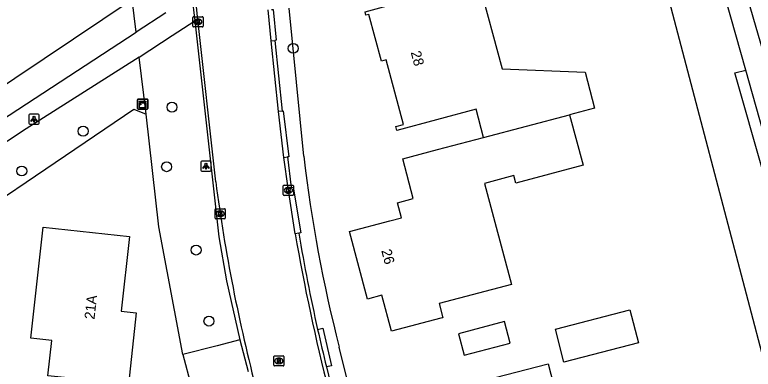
# Model space of a CAD drawing. Extents: x 162157 to 163165, y 378998 to 380775.
# Drawn here: x 162660.8 to 162733.3, y 380410.9 to 380445.7 of the extents above; entities that cross this region are included whole.
import ezdxf

# ---------------------------------------------------------------- set-up
doc = ezdxf.new("R2010")
doc.units = 0
for name, color, linetype in [('IMGEO_Boom', 7, 'Continuous'), ('IMGEO_Gemengd_bos', 7, 'Continuous'), ('IMGEO_Groenvoorziening', 7, 'Continuous'), ('IMGEO_Hek', 7, 'Continuous'), ('IMGEO_Kast', 7, 'Continuous'), ('IMGEO_Kolk', 7, 'Continuous'), ('IMGEO_Lichtpunt', 7, 'Continuous'), ('IMGEO_Pand', 7, 'Continuous'), ('IMGEO_Pand_nummerreeks', 7, 'Continuous'), ('IMGEO_Rijbaan_lokaal_gesloten', 7, 'Continuous'), ('IMGEO_Rijbaan_lokaal_open', 7, 'Continuous'), ('IMGEO_Rioolput', 7, 'Continuous'), ('IMGEO_Voetpad_halfverhard', 7, 'Continuous'), ('IMGEO_Voetpad_open', 7, 'Continuous')]:
    doc.layers.add(name, color=color, linetype=linetype)

msp = doc.modelspace()

# ---------------------------------------------------------------- linework, layer by layer
at = {"layer": 'IMGEO_Boom'}
for centre in [(162688.13, 380442.41), (162676.236, 380436.636), (162667.518, 380434.283), (162675.71, 380430.795), (162661.503, 380430.375), (162678.6, 380422.62), (162679.864, 380415.65)]:
    msp.add_circle(centre, 0.489, dxfattribs=at)
at = {"layer": 'IMGEO_Gemengd_bos'}
for points in [[(162732.512, 380440.284), (162726.017, 380463.29), (162725.222, 380467.154)], [(162794.037, 380217.15), (162795.456, 380217.538), (162786.56, 380250), (162786.126, 380251.585), (162745.395, 380400.219), (162739.025, 380425.583), (162728.963, 380460.227), (162727.791, 380464.262)], [(162739.846, 380409.655), (162737.08, 380420.274), (162731.457, 380440.006), (162732.512, 380440.284)], [(162794.037, 380217.15), (162784.914, 380250), (162784.538, 380251.354), (162744.134, 380396.843), (162740.791, 380409.902), (162740.789, 380409.911), (162737.886, 380421.251), (162732.513, 380440.281), (162732.512, 380440.284)]]:
    msp.add_lwpolyline(points, dxfattribs=at)
at = {"layer": 'IMGEO_Groenvoorziening'}
for points in [[(162613.427, 380456.794), (162617.964, 380424.039), (162634.993, 380422.187), (162672.345, 380447.227)], [(162672.73, 380443.999), (162672.345, 380447.227)], [(162673.692, 380435.944), (162673.022, 380441.552)], [(162645.264, 380394.472), (162647.636, 380419.636), (162649.415, 380420.824), (162672.481, 380436.433), (162673.692, 380435.944)], [(162677.305, 380412.375), (162674.933, 380424.891), (162673.692, 380435.944)]]:
    msp.add_lwpolyline(points, dxfattribs=at)
at = {"layer": 'IMGEO_Hek'}
msp.add_lwpolyline([(162778.738, 380250.508), (162768.177, 380283.038), (162722.067, 380458.358), (162720.737, 380463.414)], dxfattribs=at)
at = {"layer": 'IMGEO_Kast'}
for p, q in [((162672.937, 380437.438), (162673.778, 380437.438)), ((162673.778, 380437.438), (162672.937, 380437.438)), ((162672.862, 380436.513), (162672.862, 380437.354)), ((162672.862, 380437.354), (162672.862, 380436.513)), ((162673.862, 380437.363), (162673.862, 380436.522)), ((162673.862, 380436.522), (162673.862, 380437.363)), ((162673.787, 380436.438), (162672.946, 380436.438)), ((162672.946, 380436.438), (162673.787, 380436.438))]:
    msp.add_line(p, q, dxfattribs=at)
for points in [[(162673.057, 380437.228), (162673.657, 380437.228), (162673.657, 380437.143), (162673.057, 380437.143), (162673.057, 380437.228)], [(162673.057, 380437.053), (162673.657, 380437.053), (162673.657, 380436.564), (162673.057, 380436.564), (162673.057, 380437.053)]]:
    msp.add_lwpolyline(points, dxfattribs=at)
msp.add_circle((162673.141, 380436.902), 0.0377, dxfattribs=at)
for centre, start, end in [((162672.94, 380437.36), 92.4484, 184.28452), ((162672.94, 380437.36), 92.4484, 184.28452), ((162673.784, 380437.36), 2.4484, 94.28452), ((162673.784, 380437.36), 2.4484, 94.28452), ((162672.94, 380436.516), 182.4484, 274.28452), ((162672.94, 380436.516), 182.4484, 274.28452), ((162673.784, 380436.516), 272.4484, 4.28452), ((162673.784, 380436.516), 272.4484, 4.28452)]:
    msp.add_arc(centre, 0.0779, start, end, dxfattribs=at)
at = {"layer": 'IMGEO_Kolk'}
for p, q in [((162678.278, 380444.583), (162678.278, 380445.435)), ((162678.353, 380445.509), (162679.205, 380445.509)), ((162679.279, 380445.435), (162679.279, 380444.583)), ((162678.789, 380444.729), (162678.764, 380444.729)), ((162678.766, 380445.289), (162678.791, 380445.289)), ((162679.205, 380444.509), (162678.353, 380444.509)), ((162687.155, 380428.058), (162687.155, 380428.91)), ((162687.23, 380428.984), (162688.082, 380428.984)), ((162687.643, 380428.764), (162687.668, 380428.764)), ((162688.156, 380428.91), (162688.156, 380428.058)), ((162687.666, 380428.204), (162687.641, 380428.204)), ((162688.082, 380427.984), (162687.23, 380427.984)), ((162680.465, 380425.753), (162680.465, 380426.605)), ((162680.54, 380426.679), (162681.392, 380426.679)), ((162681.466, 380426.605), (162681.466, 380425.753)), ((162680.976, 380425.899), (162680.951, 380425.899)), ((162680.953, 380426.459), (162680.978, 380426.459)), ((162681.392, 380425.679), (162680.54, 380425.679))]:
    msp.add_line(p, q, dxfattribs=at)
for points in [[(162678.278, 380444.583), (162678.278, 380445.435)], [(162678.353, 380445.509), (162679.205, 380445.509)], [(162679.279, 380445.435), (162679.279, 380444.583)], [(162678.599, 380445.209), (162678.722, 380445.209), (162678.722, 380445.058), (162678.852, 380445.209), (162679.016, 380445.209), (162678.87, 380445.058), (162679.023, 380444.809), (162678.871, 380444.809), (162678.786, 380444.973), (162678.722, 380444.906), (162678.722, 380444.809), (162678.599, 380444.809), (162678.599, 380445.209)], [(162679.205, 380444.509), (162678.353, 380444.509)], [(162687.155, 380428.058), (162687.155, 380428.91)], [(162687.23, 380428.984), (162688.082, 380428.984)], [(162688.156, 380428.91), (162688.156, 380428.058)], [(162687.476, 380428.684), (162687.599, 380428.684), (162687.599, 380428.533), (162687.729, 380428.684), (162687.893, 380428.684), (162687.747, 380428.533), (162687.9, 380428.284), (162687.748, 380428.284), (162687.663, 380428.448), (162687.599, 380428.381), (162687.599, 380428.284), (162687.476, 380428.284), (162687.476, 380428.684)], [(162688.082, 380427.984), (162687.23, 380427.984)], [(162680.465, 380425.753), (162680.465, 380426.605)], [(162680.54, 380426.679), (162681.392, 380426.679)], [(162681.466, 380426.605), (162681.466, 380425.753)], [(162680.786, 380426.379), (162680.909, 380426.379), (162680.909, 380426.228), (162681.039, 380426.379), (162681.203, 380426.379), (162681.057, 380426.228), (162681.21, 380425.979), (162681.058, 380425.979), (162680.973, 380426.143), (162680.909, 380426.076), (162680.909, 380425.979), (162680.786, 380425.979), (162680.786, 380426.379)], [(162681.392, 380425.679), (162680.54, 380425.679)]]:
    msp.add_lwpolyline(points, dxfattribs=at)
for centre, start, end in [((162678.355, 380445.433), 91.55205, 178.44795), ((162678.355, 380445.433), 91.55205, 178.44795), ((162679.203, 380445.433), 1.55205, 88.44795), ((162679.203, 380445.433), 1.55205, 88.44795), ((162678.355, 380444.585), 181.55205, 268.44795), ((162678.355, 380444.585), 181.55205, 268.44795), ((162679.203, 380444.585), 271.55205, 358.44795), ((162679.203, 380444.585), 271.55205, 358.44795), ((162687.232, 380428.908), 91.55205, 178.44795), ((162687.232, 380428.908), 91.55205, 178.44795), ((162688.08, 380428.908), 1.55205, 88.44795), ((162688.08, 380428.908), 1.55205, 88.44795), ((162687.232, 380428.06), 181.55205, 268.44795), ((162687.232, 380428.06), 181.55205, 268.44795), ((162688.08, 380428.06), 271.55205, 358.44795), ((162688.08, 380428.06), 271.55205, 358.44795), ((162680.542, 380426.603), 91.55205, 178.44795), ((162680.542, 380426.603), 91.55205, 178.44795), ((162681.39, 380426.603), 1.55205, 88.44795), ((162681.39, 380426.603), 1.55205, 88.44795), ((162680.542, 380425.755), 181.55205, 268.44795), ((162680.542, 380425.755), 181.55205, 268.44795), ((162681.39, 380425.755), 271.55205, 358.44795), ((162681.39, 380425.755), 271.55205, 358.44795)]:
    msp.add_arc(centre, 0.0765, start, end, dxfattribs=at)
for centre, major_axis, ratio, start_param, end_param in [((162678.765, 380445.009), (-0.387, 0.002), 0.722429, 4.712389, 7.853982), ((162678.79, 380445.009), (-0.39, 0.002), 0.717154, 1.570796, 4.712389), ((162687.642, 380428.484), (-0.387, 0.002), 0.722429, 4.712389, 7.853982), ((162687.667, 380428.484), (-0.39, 0.002), 0.717154, 1.570796, 4.712389), ((162680.952, 380426.179), (-0.387, 0.002), 0.722429, 4.712389, 7.853982), ((162680.977, 380426.179), (-0.39, 0.002), 0.717154, 1.570796, 4.712389)]:
    msp.add_ellipse(centre, major_axis=major_axis, ratio=ratio, start_param=start_param, end_param=end_param, dxfattribs=at)
at = {"layer": 'IMGEO_Lichtpunt'}
for p, q in [((162663.107, 380435.956), (162662.299, 380435.956)), ((162663.107, 380435.956), (162662.299, 380435.956)), ((162662.205, 380435.861), (162662.205, 380435.054)), ((162662.205, 380435.861), (162662.205, 380435.054)), ((162663.201, 380435.054), (162663.201, 380435.861)), ((162663.201, 380435.054), (162663.201, 380435.861)), ((162662.299, 380434.96), (162663.107, 380434.96)), ((162662.299, 380434.96), (162663.107, 380434.96)), ((162679.069, 380431.251), (162679.069, 380430.444)), ((162679.069, 380431.251), (162679.069, 380430.444)), ((162679.971, 380431.346), (162679.163, 380431.346)), ((162679.971, 380431.346), (162679.163, 380431.346)), ((162680.065, 380430.444), (162680.065, 380431.251)), ((162680.065, 380430.444), (162680.065, 380431.251)), ((162679.163, 380430.35), (162679.971, 380430.35)), ((162679.163, 380430.35), (162679.971, 380430.35))]:
    msp.add_line(p, q, dxfattribs=at)
for points in [[(162662.579, 380435.525), (162662.618, 380435.497), (162662.43, 380435.235), (162662.392, 380435.262), (162662.579, 380435.525)], [(162662.681, 380435.477), (162662.728, 380435.477), (162662.728, 380435.155), (162662.681, 380435.155), (162662.681, 380435.477)], [(162662.791, 380435.497), (162662.829, 380435.524), (162663.016, 380435.262), (162662.977, 380435.234), (162662.791, 380435.497)], [(162679.443, 380430.915), (162679.482, 380430.887), (162679.294, 380430.625), (162679.256, 380430.652), (162679.443, 380430.915)], [(162679.655, 380430.887), (162679.693, 380430.914), (162679.88, 380430.652), (162679.841, 380430.624), (162679.655, 380430.887)], [(162679.545, 380430.867), (162679.592, 380430.867), (162679.592, 380430.545), (162679.545, 380430.545), (162679.545, 380430.867)]]:
    msp.add_lwpolyline(points, dxfattribs=at)
for centre in [(162662.704, 380435.659), (162679.568, 380431.049)]:
    msp.add_circle(centre, 0.0994, dxfattribs=at)
for centre, start, end in [((162662.299, 380435.861), 90, 180), ((162662.299, 380435.861), 90, 180), ((162663.107, 380435.861), 0, 90), ((162663.107, 380435.861), 0, 90), ((162662.299, 380435.054), 180, 270), ((162662.299, 380435.054), 180, 270), ((162663.107, 380435.054), 270, 0), ((162663.107, 380435.054), 270, 360), ((162679.163, 380431.251), 90, 180), ((162679.163, 380431.251), 90, 180), ((162679.971, 380431.251), 0, 90), ((162679.971, 380431.251), 0, 90), ((162679.163, 380430.444), 180, 270), ((162679.163, 380430.444), 180, 270), ((162679.971, 380430.444), 270, 0), ((162679.971, 380430.444), 270, 360)]:
    msp.add_arc(centre, 0.0946, start, end, dxfattribs=at)
at = {"layer": 'IMGEO_Pand'}
for points in [[(162696.861, 380452.692), (162702.175, 380454.118), (162703.738, 380448.295), (162706.318, 380448.988), (162708.621, 380440.412), (162716.751, 380440.068), (162717.69, 380436.537), (162715.243, 380435.893)], [(162706.789, 380433.67), (162706.058, 380436.437), (162698.3, 380434.356), (162698.195, 380434.749), (162698.934, 380434.947), (162697.232, 380441.287), (162696.774, 380441.164), (162695.547, 380445.737), (162695.259, 380445.659), (162695.169, 380445.994), (162698.424, 380446.868), (162696.861, 380452.692)], [(162715.243, 380435.893), (162716.554, 380430.941), (162709.956, 380429.188), (162709.761, 380429.922), (162706.898, 380429.165), (162709.524, 380419.236), (162702.437, 380417.361), (162702.801, 380415.984), (162702.601, 380415.931), (162697.767, 380414.652), (162696.833, 380418.182), (162695.411, 380417.806), (162693.655, 380424.439), (162697.616, 380425.487), (162698.745, 380425.786), (162698.354, 380427.266), (162699.909, 380427.691), (162698.881, 380431.579), (162702.293, 380432.481), (162706.789, 380433.67)], [(162706.789, 380433.67), (162715.243, 380435.893)], [(162664.053, 380410.294), (162664.435, 380413.763), (162662.403, 380413.987), (162663.051, 380419.867), (162663.601, 380424.868), (162672.065, 380423.935), (162671.259, 380416.618), (162672.73, 380416.456), (162671.955, 380409.424), (162666.986, 380409.971), (162664.053, 380410.294)], [(162713.848, 380414.862), (162721.142, 380416.758), (162721.981, 380413.529), (162714.687, 380411.633), (162713.848, 380414.862)], [(162704.325, 380414.413), (162704.884, 380412.297), (162709.413, 380413.494), (162708.853, 380415.609), (162704.325, 380414.413)], [(162702.207, 380399.787), (162701.196, 380399.524), (162699.041, 380407.797), (162703.88, 380409.057), (162713.128, 380411.466), (162714.149, 380407.547), (162708.903, 380406.18), (162710.038, 380401.823)]]:
    msp.add_lwpolyline(points, dxfattribs=at)
at = {"layer": 'IMGEO_Rijbaan_lokaal_gesloten'}
for points in [[(162678.198, 380447.57), (162678.473, 380445.123)], [(162680.525, 380429.323), (162678.724, 380445.517), (162678.557, 380447.491), (162678.535, 380447.716)], [(162685.972, 380443.152), (162685.661, 380446.176)], [(162678.473, 380445.123), (162680.83, 380423.933), (162681.587, 380419.614), (162682.894, 380413.81)], [(162686.685, 380436.218), (162685.972, 380443.152)], [(162687.211, 380431.709), (162686.685, 380436.218)], [(162687.622, 380428.707), (162687.211, 380431.709)], [(162688.33, 380424.21), (162687.622, 380428.707)], [(162682.894, 380413.81), (162683.705, 380410.707)]]:
    msp.add_lwpolyline(points, dxfattribs=at)
for centre, radius, start, end in [((162845.64, 380450.967), 166.527, 187.46797, 194.71182), ((162875.43, 380455.958), 189.775, 189.6306, 194.40292)]:
    msp.add_arc(centre, radius, start, end, dxfattribs=at)
at = {"layer": 'IMGEO_Rijbaan_lokaal_open'}
for points in [[(162685.972, 380443.152), (162686.321, 380443.188)], [(162686.321, 380443.188), (162687.032, 380436.26)], [(162687.032, 380436.26), (162686.685, 380436.218)], [(162687.211, 380431.709), (162687.559, 380431.751)], [(162687.559, 380431.751), (162687.938, 380428.76)], [(162687.622, 380428.707), (162687.938, 380428.76)], [(162688.674, 380424.267), (162688.33, 380424.21)], [(162691.381, 380411.149), (162691.958, 380408.844)]]:
    msp.add_lwpolyline(points, dxfattribs=at)
for centre, radius, start, end in [((162876.499, 380456.164), 190.514, 189.6381, 192.52801), ((162878.109, 380456.625), 192.185, 192.55808, 193.68738)]:
    msp.add_arc(centre, radius, start, end, dxfattribs=at)
at = {"layer": 'IMGEO_Rioolput'}
for p, q in [((162686.221, 380411.32), (162686.221, 380412.172)), ((162686.296, 380412.246), (162687.148, 380412.246)), ((162687.222, 380412.172), (162687.222, 380411.32)), ((162686.732, 380411.466), (162686.707, 380411.466)), ((162686.709, 380412.026), (162686.734, 380412.026)), ((162687.148, 380411.246), (162686.296, 380411.246))]:
    msp.add_line(p, q, dxfattribs=at)
for points in [[(162686.221, 380411.32), (162686.221, 380412.172)], [(162686.296, 380412.246), (162687.148, 380412.246)], [(162687.222, 380412.172), (162687.222, 380411.32)], [(162686.81, 380411.944), (162686.558, 380411.946), (162686.558, 380411.546)], [(162686.558, 380411.546), (162686.682, 380411.546), (162686.682, 380411.708), (162686.693, 380411.708)], [(162686.736, 380411.865), (162686.682, 380411.865), (162686.682, 380411.784)], [(162686.682, 380411.784), (162686.734, 380411.784)], [(162686.74, 380411.679), (162686.811, 380411.546), (162686.951, 380411.546), (162686.886, 380411.672)], [(162687.148, 380411.246), (162686.296, 380411.246)]]:
    msp.add_lwpolyline(points, dxfattribs=at)
for centre, radius, start, end in [((162686.298, 380412.17), 0.0765, 91.55205, 178.44795), ((162686.298, 380412.17), 0.0765, 91.55205, 178.44795), ((162687.146, 380412.17), 0.0765, 1.55205, 88.44795), ((162687.146, 380412.17), 0.0765, 1.55205, 88.44795), ((162686.692, 380411.655), 0.0533, 26.02933, 88.69889), ((162686.718, 380411.973), 0.19, 274.7715, 282.96867), ((162686.742, 380411.769), 0.0964, 77.00612, 93.18647), ((162686.756, 380411.826), 0.0378, 276.66336, 79.67722), ((162686.809, 380411.834), 0.109, 350.36119, 89.41601), ((162686.807, 380411.834), 0.112, 277.58423, 350.98172), ((162686.791, 380411.619), 0.108, 29.51342, 73.79051), ((162686.298, 380411.322), 0.0765, 181.55205, 268.44795), ((162686.298, 380411.322), 0.0765, 181.55205, 268.44795), ((162687.146, 380411.322), 0.0765, 271.55205, 358.44795), ((162687.146, 380411.322), 0.0765, 271.55205, 358.44795)]:
    msp.add_arc(centre, radius, start, end, dxfattribs=at)
for centre, major_axis, ratio, start_param, end_param in [((162686.708, 380411.746), (-0.387, 0.002), 0.722429, 4.712389, 7.853982), ((162686.733, 380411.746), (-0.39, 0.002), 0.717154, 1.570796, 4.712389)]:
    msp.add_ellipse(centre, major_axis=major_axis, ratio=ratio, start_param=start_param, end_param=end_param, dxfattribs=at)
at = {"layer": 'IMGEO_Voetpad_halfverhard'}
for points in [[(162675.637, 380445.897), (162672.73, 380443.999)], [(162673.022, 380441.552), (162676.252, 380443.668), (162678.473, 380445.123)], [(162623.274, 380414.017), (162627.726, 380415.861), (162631.647, 380417.623), (162633.167, 380418.424), (162638.721, 380421.787), (162672.73, 380443.999)], [(162673.022, 380441.552), (162661.944, 380434.51), (162649.279, 380426.188), (162642.619, 380421.799)]]:
    msp.add_lwpolyline(points, dxfattribs=at)
at = {"layer": 'IMGEO_Voetpad_open'}
for points in [[(162686.01, 380446.212), (162686.159, 380446.227), (162686.47, 380443.203), (162686.321, 380443.188)], [(162689.172, 380431.822), (162687.725, 380446.347)], [(162687.032, 380436.26), (162687.154, 380436.275), (162687.707, 380431.769), (162687.559, 380431.751)], [(162687.938, 380428.76), (162688.115, 380428.789), (162688.869, 380424.3), (162688.674, 380424.267)], [(162690.521, 380414.838), (162691.039, 380414.944), (162691.875, 380411.255), (162691.381, 380411.149)], [(162682.894, 380413.81), (162680.665, 380413.238), (162677.305, 380412.375)], [(162723.095, 380296.969), (162697.063, 380396.837), (162695.162, 380403), (162692.636, 380413.099)], [(162677.305, 380412.375), (162678.13, 380409.289)]]:
    msp.add_lwpolyline(points, dxfattribs=at)
msp.add_arc((162828.071, 380447.838), 139.819, 186.57761, 194.38628, dxfattribs=at)

# ---------------------------------------------------------------- texts
at = {"layer": 'IMGEO_Pand_nummerreeks'}
for s, rotation, p in [('28', 285.027, (162699.644, 380442.02)), ('26', 284.82814, (162696.757, 380422.567)), ('21A', 83.71396, (162668.632, 380415.778))]:
    msp.add_text(s, height=1, rotation=rotation, dxfattribs=at).set_placement(p)

doc.saveas('drawing.dxf')
